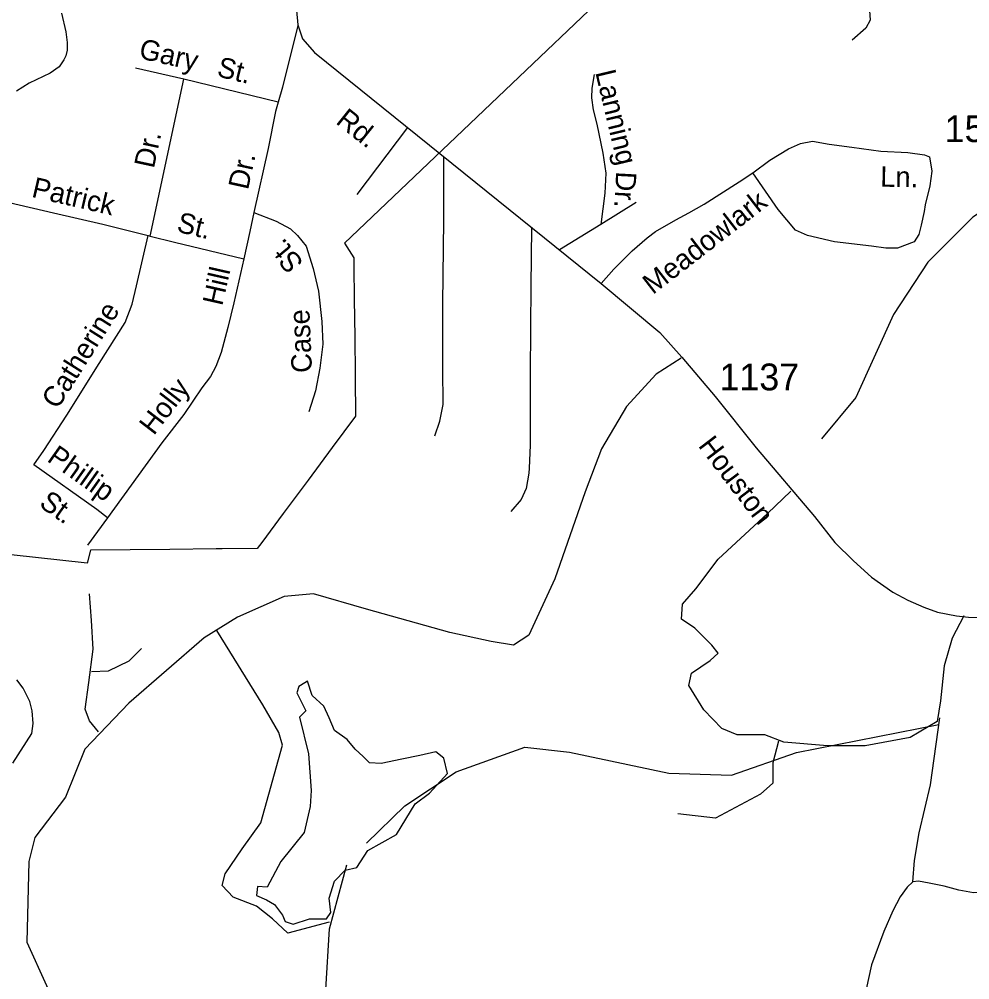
# Model space of a CAD drawing. Extents: x 990631 to 1056237, y 535999 to 585651.
# Drawn here: x 1044054 to 1048486, y 554992 to 559473 of the extents above; entities that cross this region are included whole.
import ezdxf

# ---------------------------------------------------------------- set-up
doc = ezdxf.new("R2010")
doc.units = 0
for name, color, linetype in [('Exist Boundary Political City Limit New', 7, 'Continuous'), ('Exist Hydrographic Creek Single Shore', 7, 'Continuous'), ('Exist Hydrographic Lake Shore', 7, 'Continuous'), ('Exist Road Non-System Type 51', 7, 'Continuous'), ('Exist Road Non-System Type 51 Label', 7, 'Continuous'), ('Exist Road Primary Interstate Ramp 1 Lane Attributed', 7, 'Continuous'), ('Exist Road Secondary Type 51 Attributed', 7, 'Continuous'), ('Exist Road Secondary Type 51 Label', 7, 'Continuous'), ('Exist Road Secondary Type 51 Number Label', 7, 'Continuous')]:
    doc.layers.add(name, color=color, linetype=linetype)

msp = doc.modelspace()

# ---------------------------------------------------------------- linework, layer by layer
at = {"layer": 'Exist Boundary Political City Limit New'}
msp.add_lwpolyline([(1047556.4, 560320.3), (1045570.9, 558429), (1045614.5, 558359.8), (1045615, 558319.1), (1045616.7, 558167.8), (1045618.7, 557989.6), (1045620.6, 557815.1), (1045620.8, 557803.8), (1045622.8, 557620.7), (1045514.2, 557474.8), (1045401.4, 557323.1), (1045285.1, 557166.7), (1045185.2, 557032.3), (1045164.2, 557004.1), (1045000, 557002.4), (1044972.8, 557002.1), (1044757, 556999.8), (1044386.5, 556996.4), (1044370.9, 556935.4), (1042951.9, 557090.9)], dxfattribs=at)
at = {"layer": 'Exist Hydrographic Creek Single Shore'}
for points in [[(1045672.9, 555629.5), (1045852.7, 555802.9), (1046091.4, 555962.2), (1046412.2, 556077.2), (1046619.6, 556053.3), (1047083.4, 555955.4), (1047375.1, 555946.2), (1047678.7, 556051.7), (1048341.5, 556182.7)], [(1044652.4, 552955.3), (1044720.5, 552996.7), (1044766.1, 553120.5), (1044814.6, 553592.1), (1044940.6, 553881.6), (1045327.2, 554234.9), (1045484.6, 554464.7), (1045517.2, 554697.1), (1045483.5, 554947.2), (1045500.9, 555229.1), (1045581.2, 555527.7)]]:
    msp.add_lwpolyline(points, dxfattribs=at)
at = {"layer": 'Exist Hydrographic Lake Shore'}
msp.add_lwpolyline([(1045211.1, 555423.5), (1045165.1, 555427.6), (1045160.9, 555385.8), (1045206.9, 555364.9), (1045244.5, 555344), (1045282.1, 555293.8), (1045294.7, 555264.5), (1045332.3, 555252), (1045407.6, 555277.1), (1045487, 555277.1), (1045507.9, 555306.4), (1045499.5, 555373.3), (1045524.6, 555452.7), (1045574.8, 555502.9), (1045629.1, 555515.5), (1045679.3, 555594.9), (1045746.1, 555632.6), (1045813, 555670.2), (1045900.8, 555812.4), (1045967.7, 555862.6), (1046051.3, 555954.6), (1046034.6, 556025.7), (1045997, 556054.9), (1045921.7, 556038.2), (1045838.1, 556021.5), (1045742, 556000.6), (1045687.6, 556004.8), (1045658.4, 556034), (1045620.7, 556067.5), (1045583.1, 556113.5), (1045524.6, 556155.3), (1045499.5, 556213.9), (1045474.4, 556268.2), (1045420.1, 556318.4), (1045399.2, 556385.3), (1045386.7, 556376.9), (1045357.4, 556360.2), (1045349, 556330.9), (1045390.8, 556247.3), (1045361.6, 556218), (1045403.4, 556046.6), (1045415.9, 555875.1), (1045411.7, 555799.8), (1045382.5, 555678.6), (1045273.8, 555544.7)], close=True, dxfattribs=at)
at = {"layer": 'Exist Road Non-System Type 51'}
for p, q in [((1044822.7, 559192.9), (1044596, 559244.1)), ((1044665.1, 558461.4), (1044822.7, 559192.9)), ((1045261.5, 559086.6), (1044822.7, 559192.9)), ((1045864.9, 558967.3), (1045627.9, 558654.7)), ((1046931.6, 558618.8), (1046766.1, 558516.1)), ((1046766.1, 558516.1), (1046572.8, 558397.2)), ((1044655.1, 558463.8), (1044665.1, 558461.4)), ((1044466.7, 557146.9), (1044372.5, 557019.8))]:
    msp.add_line(p, q, dxfattribs=at)
for points in [[(1047454.4, 560257.1), (1047460.1, 560124.9), (1047468.5, 560074.6), (1047479.8, 560050.3), (1047504.9, 560025.4), (1047532.7, 560012.4), (1047592.1, 559994.6), (1047659.8, 559986.5), (1047717.3, 559968.5), (1047743.1, 559959.8), (1047760.6, 559945.2), (1047787.4, 559906.3), (1047822.9, 559829.1), (1047857.7, 559788), (1047934.7, 559697.4), (1047990.4, 559621.7), (1048010.8, 559574.9), (1048017.6, 559534.7), (1048021.5, 559468.4), (1048002.3, 559431.2), (1047938.4, 559375)], [(1051820.5, 559608.9), (1051669.3, 559558.4), (1051366.7, 559550), (1051047.4, 559491.2), (1050862.5, 559449.2), (1050551.6, 559289.4), (1050030.6, 559070.8), (1049786.9, 558961.5), (1049391.9, 558911.1), (1049081, 558835.4), (1048820.5, 558759.8), (1048501.1, 558549.6), (1048291, 558339.4), (1048131.4, 558095.6), (1047954.9, 557708.9), (1047795.2, 557515.5)], [(1044252.1, 559501.3), (1044271.3, 559414.7), (1044277.7, 559364.5), (1044278.6, 559328.3), (1044271.7, 559302.6), (1044263.1, 559282.8), (1044240, 559251.5), (1044199, 559220.9), (1044101.4, 559174), (1044042.3, 559137.8)], [(1045352.9, 559443.5), (1045281.7, 559156), (1045261.5, 559086.6)], [(1046734.6, 559215.6), (1046724.5, 559151.8), (1046722.9, 559105.8), (1046731.2, 559049.6), (1046747.1, 558983.1), (1046774.8, 558848.1), (1046789.9, 558755.5), (1046784.8, 558661.6), (1046766.1, 558516.1)], [(1045261.5, 559086.6), (1045250, 559043), (1045214.5, 558870.1), (1045148.9, 558571.9)], [(1045992, 557530.2), (1046016.1, 557597.5), (1046030.7, 557675), (1046030.1, 557843.3), (1046029.8, 558147.4), (1046034.2, 558533.5), (1046034.9, 558830.4)], [(1043847, 558789.8), (1043883.8, 558748.6), (1043908.4, 558711.7), (1043925.4, 558677.2), (1043936.2, 558640.9), (1043955.7, 558626.1), (1044007.6, 558618.5), (1044214.1, 558569.9), (1044444.7, 558516.5), (1044655.1, 558463.8)], [(1045148.9, 558571.9), (1045130, 558482.5), (1045101.9, 558355.4)], [(1045148.9, 558571.9), (1045251.7, 558530.6), (1045318.6, 558494.5), (1045351.5, 558463.4), (1045392, 558414.2), (1045424.7, 558310.9), (1045449.3, 558204.1), (1045464.7, 558063.6), (1045469.4, 557957.2), (1045455.7, 557845.7), (1045436.4, 557740.2), (1045405.2, 557641.2)], [(1046443, 558501.6), (1046440.5, 558226.4), (1046438.5, 558036.3), (1046437.4, 557812.1), (1046436.8, 557486), (1046431.4, 557378)], [(1044466.7, 557146.9), (1044415.9, 557186.6), (1044122.4, 557394.1), (1044168.5, 557460.6), (1044275.9, 557625.3), (1044427.8, 557866.6), (1044548.1, 558058.8), (1044580.8, 558143.8), (1044601.6, 558229.2), (1044655.1, 558463.8)], [(1044665.1, 558461.4), (1044778.1, 558433.7), (1045101.9, 558355.4)], [(1045101.9, 558355.4), (1045055.3, 558150.6), (1045027.6, 558035.6), (1044995.8, 557918.3), (1044971.7, 557853.2), (1044946.2, 557805.9), (1044906.5, 557753.3), (1044822.4, 557629.7), (1044720, 557496.9), (1044466.7, 557146.9)], [(1047140.8, 557891.9), (1047023.8, 557816.6), (1046885.8, 557666.1), (1046768.8, 557469.5), (1046693.6, 557268.8), (1046551.4, 556863.1), (1046430.2, 556599.7), (1046359.1, 556553.7), (1046254.6, 556570.4), (1046062.3, 556612.2), (1045673.6, 556720.9), (1045427, 556792), (1045289, 556779.5), (1045071.6, 556683.3), (1044917, 556587.1), (1044565.8, 556281.8), (1044361, 556068.6), (1044269.9, 555844.4), (1044127.8, 555656.2), (1044098.5, 555543.3), (1044090.1, 555166.9), (1044182.1, 554966.2), (1044286.6, 554737.4), (1044391.1, 554632.9)], [(1046431.4, 557378), (1046430.8, 557356.1), (1046418.3, 557284.5), (1046394.7, 557233.1), (1046347, 557176.7)], [(1048459.1, 556690.6), (1048404.7, 556586), (1048367.1, 556456.4), (1048350.4, 556293.3), (1048333.7, 556197.1), (1048208.3, 556121.8), (1047999.3, 556084.2), (1047823.7, 556084.2), (1047618.9, 556100.9), (1047531.1, 556134.4), (1047401.5, 556134.4), (1047330.4, 556163.7), (1047246.8, 556251.5), (1047175.8, 556364.4), (1047188.3, 556422.9), (1047276.1, 556481.5), (1047313.7, 556515), (1047284.5, 556552.6), (1047205, 556632), (1047142.3, 556673.9), (1047146.5, 556745), (1047209.2, 556816.1), (1047313.7, 556954.1), (1047543.6, 557167.3), (1047652.3, 557271.9)], [(1044424.5, 556149.3), (1044382.7, 556199.5), (1044361.8, 556253.8), (1044378.6, 556379.3), (1044399.5, 556534), (1044391.1, 556667.8), (1044382.7, 556793.3)], [(1045498.9, 555260.2), (1045306.6, 555210), (1045235.5, 555276.9), (1045160.3, 555335.5), (1045051.6, 555377.3), (1045001.4, 555431.7), (1045014, 555486), (1045093.4, 555603.1), (1045181.2, 555724.4), (1045281.5, 556086.5), (1045264.8, 556145.1), (1045189.5, 556274.7), (1044976.3, 556621.8)], [(1044391.1, 556429.5), (1044470.5, 556433.7), (1044566.7, 556479.7), (1044625.2, 556538.2)], [(1048220.8, 555449.3), (1048229.2, 555549), (1048250.5, 555677.1), (1048303.8, 555901.2), (1048346.2, 556213.9)], [(1047593.8, 556105.1), (1047568.7, 556004.8), (1047568.7, 555908.6), (1047510.2, 555858.4), (1047301.2, 555745.5), (1047125.6, 555766.4)], [(1048561.7, 555408.4), (1048543.3, 555399), (1048503.3, 555398.2), (1048435.7, 555410.4), (1048366.2, 555428.8), (1048296.7, 555443), (1048246.9, 555452.6), (1048220.8, 555449.3), (1048193.9, 555424.3), (1048162.4, 555379.3), (1048128.4, 555314.3), (1048085.3, 555217.6), (1048028.1, 555061.3), (1048002.6, 554948.1), (1047978.5, 554824.8), (1047953.1, 554715.4), (1047933.1, 554656), (1047909.6, 554612.7), (1047899.4, 554603.1)]]:
    msp.add_lwpolyline(points, dxfattribs=at)
at = {"layer": 'Exist Road Primary Interstate Ramp 1 Lane Attributed'}
msp.add_lwpolyline([(1044024.3, 556003.1), (1044113.1, 556140.9), (1044120.1, 556187.7), (1044115.2, 556246.5), (1044103.7, 556290.5), (1044072.9, 556352.6), (1044043, 556391)], dxfattribs=at)
at = {"layer": 'Exist Road Secondary Type 51 Attributed'}
for points in [[(1044875.9, 561701), (1045534.2, 560996.2), (1045447.6, 560919.2), (1045373.1, 560849.4), (1045338.2, 560812.1), (1045308.1, 560770), (1045294.9, 560741.2), (1045276.8, 560689.3), (1045277.4, 560641.3), (1045278.2, 560543.2), (1045280, 560359.3), (1045332.8, 559686.8), (1045347.1, 559513.5), (1045353.6, 559446.4), (1045374.9, 559381), (1045430.5, 559317.2), (1046767.2, 558240.6)], [(1047474.9, 558756.9), (1047554.8, 558814.9), (1047641.2, 558868.5), (1047696.4, 558892.7), (1047753.4, 558904.8), (1047831.1, 558890.9), (1047936.4, 558875.4), (1048071, 558858.1), (1048197, 558851.2), (1048274.7, 558840.9), (1048298.9, 558830.5), (1048309.2, 558764.8), (1048300.6, 558695.8), (1048278.6, 558607.5)], [(1046767.2, 558240.6), (1046826.7, 558307.8), (1046911.7, 558392.9), (1046982, 558453.4), (1047021.3, 558482.9), (1047116.1, 558536.8), (1047176.6, 558569.6), (1047247.6, 558610.7), (1047410.4, 558715.2), (1047474.9, 558756.9)], [(1048278.6, 558607.5), (1048273, 558576.6), (1048259.2, 558512.7), (1048248.8, 558469.5), (1048226.6, 558435.3), (1048149.5, 558405.6), (1048095.2, 558405.6), (1048027.8, 558414.2), (1047855.2, 558434.9), (1047729.2, 558464.3), (1047673.8, 558489), (1047593, 558585.7), (1047474.9, 558756.9)], [(1046767.2, 558240.6), (1047040.9, 558011.7), (1047143.9, 557897.2), (1047299.2, 557712.3), (1047490.5, 557473.5), (1047761.9, 557152.8), (1047856.7, 557031.8), (1047945, 556946.7), (1048028.4, 556869.8), (1048128.2, 556801.1), (1048196.8, 556763.5), (1048272, 556730.7), (1048335.8, 556707.8), (1048424.1, 556689.8), (1048479.7, 556683.3), (1048798.5, 556671.8)]]:
    msp.add_lwpolyline(points, dxfattribs=at)

# ---------------------------------------------------------------- texts
at = {"layer": 'Exist Road Non-System Type 51 Label'}
for s, rotation, p in [('Gary ', 347.2748, (1044608, 559291.8)), ('St.', 346.386, (1044971.9, 559207.4)), ('Lanning', 283.4101, (1046739.9, 559225.6)), ('Dr.', 77.8422, (1044682, 558773.7)), ('Dr.', 77.5874, (1045120.9, 558673.7)), ('Patrick', 346.9473, (1044108.1, 558645)), ('Dr.', 266.8957, (1046837.8, 558764.5)), ('St.', 346.3953, (1044784.4, 558482.8)), ('St.', 129.3883, (1045383.9, 558338)), ('Hill', 77.1931, (1045000.8, 558132.5)), ('Catherine', 57.7997, (1044233, 557649.6)), ('Case', 92.5092, (1045419.9, 557825.3)), ('Holly', 52.3866, (1044681.8, 557528)), ('Phillip', 324.7309, (1044179.3, 557414.1)), ('St.', 324.7309, (1044142.3, 557203.5))]:
    msp.add_text(s, height=95, rotation=rotation, dxfattribs=at).set_placement(p)
at = {"layer": 'Exist Road Secondary Type 51 Label'}
for s, rotation, p in [('Rd.', 321.4592, (1045526.1, 558989.8)), ('Ln.', 359.1476, (1048068.6, 558691.8)), ('Meadowlark', 37.7814, (1047008.4, 558186.1)), ('Houston', 307.3365, (1047217.3, 557483.1))]:
    msp.add_text(s, height=95, rotation=rotation, dxfattribs=at).set_placement(p)
at = {"layer": 'Exist Road Secondary Type 51 Number Label'}
for s, p in [('1566', (1048369.1, 558899.9)), ('1137', (1047319.2, 557741.9))]:
    msp.add_text(s, height=125, dxfattribs=at).set_placement(p)

doc.saveas('drawing.dxf')
